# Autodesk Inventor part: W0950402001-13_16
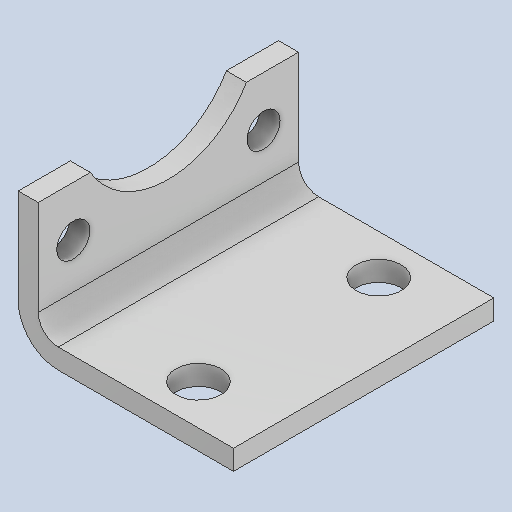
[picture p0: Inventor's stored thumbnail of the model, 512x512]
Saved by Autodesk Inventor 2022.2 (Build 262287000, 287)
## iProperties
Created: 2024-10
Part Number: W0950402001-13_16
Material: Generico
Document SubType Name: Modeling
Designer: 18907419
Density: 1 g/cm^3
Appearance: Default
Author: 18907419
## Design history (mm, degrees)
feature "Solid1"
node "Solido1"
